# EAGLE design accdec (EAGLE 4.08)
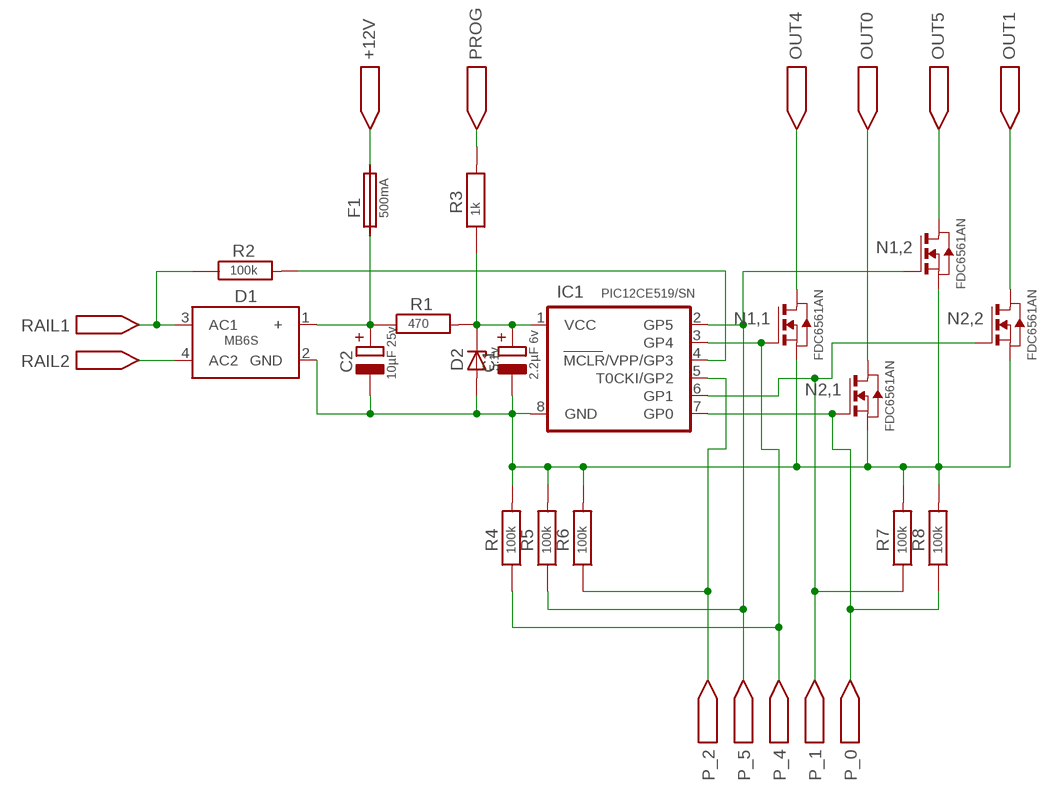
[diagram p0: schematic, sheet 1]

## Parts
+12V  PORT1*0.6  [CON_1*0.6]
C1  2.2µF 6v  ELKO_A  [CA]
C2  10µF 25v  ELKO_C  [CC]
D1  MB6S  [G1]
D2  5.1v  ZMM  [ZMM]
F1  500mA  FUSE  [1210]
IC1  PIC12CE519/SN  [SO8/SN]
N1  FDC6561AN  [SSOP6]
N2  FDC6561AN  [SSOP6]
OUT0  PORT1*0.6  [CON_1*0.6]
OUT1  PORT1*0.6  [CON_1*0.6]
OUT4  PORT1*0.6  [CON_1*0.6]
OUT5  PORT1*0.6  [CON_1*0.6]
P_0  PORT1*0.6  [CON_1*0.6]
P_1  PORT1*0.6  [CON_1*0.6]
P_2  PORT1*0.6  [CON_1*0.6]
P_4  PORT1*0.6  [CON_1*0.6]
P_5  PORT1*0.6  [CON_1*0.6]
PROG  PORT1*0.6  [CON_1*0.6]
R1  470  R-M1  [MICRO_MELF]
R2  100k  R-M1  [MICRO_MELF]
R3  1k  R-M1  [MICRO_MELF]
R4  100k  R-M1  [MICRO_MELF]
R5  100k  R-M1  [MICRO_MELF]
R6  100k  R-M1  [MICRO_MELF]
R7  100k  R-M1  [MICRO_MELF]
R8  100k  R-M1  [MICRO_MELF]
RAIL1  PORT1*0.6  [CON_1*0.6]
RAIL2  PORT1*0.6  [CON_1*0.6]

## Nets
+: C2.P$2(+) D1.1(+) F1.1 R1.P$1
DCCIN: IC1.4(MCLR/VPP/GP3) R2.P$2
F: +12V.P$1 F1.2
GND: C1.P$1(-) C2.P$1(-) D1.2(GND) D2.P$1(A) IC1.8(GND) N1.2(,2:S) N1.5(,1:S) N2.2(,2:S) N2.5(,1:S) R4.P$2 R5.P$2 R6.P$2 R7.P$2 R8.P$2
GP0: IC1.7(GP0) N2.1(,1:G) P_0.P$1 R8.P$1
GP1: IC1.6(GP1) N2.3(,2:G) P_1.P$1 R7.P$1
GP2: IC1.5(T0CKI/GP2) P_2.P$1 R6.P$1
GP4: IC1.3(GP4) N1.1(,1:G) P_4.P$1 R4.P$1
GP5: IC1.2(GP5) N1.3(,2:G) P_5.P$1 R5.P$1
OUT0: N2.6(,1:D) OUT0.P$1
OUT1: N2.4(,2:D) OUT1.P$1
OUT4: N1.6(,1:D) OUT4.P$1
OUT5: N1.4(,2:D) OUT5.P$1
PROG: PROG.P$1 R3.P$2
RAIL1: D1.3(AC1) R2.P$1 RAIL1.P$1
RAIL2: D1.4(AC2) RAIL2.P$1
VCC: C1.P$2(+) D2.P$2(K) IC1.1(VCC) R1.P$2 R3.P$1

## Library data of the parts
+12V OUT0 OUT1 OUT4 OUT5 P_0 P_1 P_2 P_4 P_5 PROG RAIL1 RAIL2 = NMRA-DCC_Decoder_Parts:PORT
C1 C2 = NMRA-DCC_Decoder_Parts:ELKO
D1 = NMRA-DCC_Decoder_Parts:MB6S: Rectifier s380 & mb6s
D2 = NMRA-DCC_Decoder_Parts:ZMM: DIODE
F1 = NMRA-DCC_Decoder_Parts:FUSE
IC1 = NMRA-DCC_Decoder_Parts:PIC12C*?: PIC12Cx5xx 8 bit Microchip Microcontroller with 2k byte PROM and 16 byte EEPROM
N1 N2 = NMRA-DCC_Decoder_Parts:FDC6561AN: FDC6561AN Dual N-Channel Logic Level PowerTrench MOSFET 2.5 A 30 V
R1-R8 = NMRA-DCC_Decoder_Parts:R-: Resistor

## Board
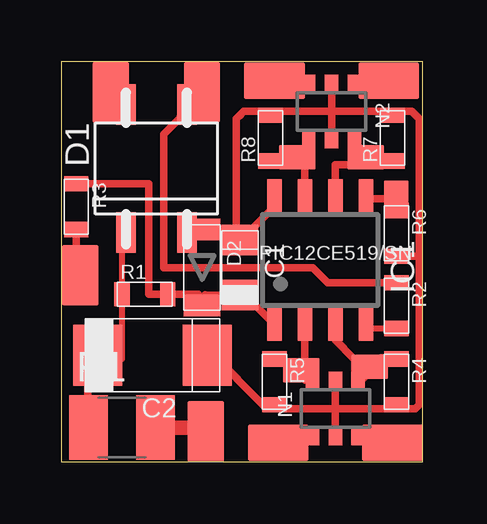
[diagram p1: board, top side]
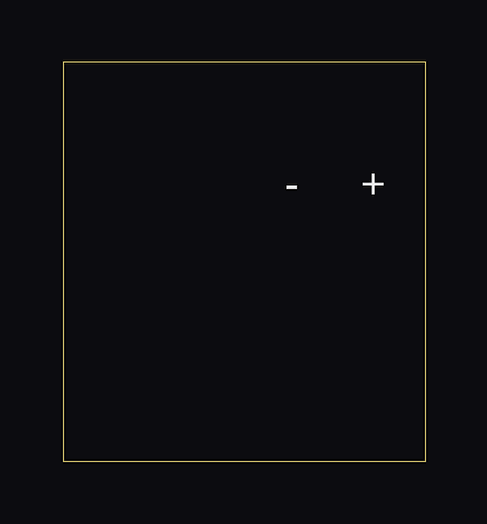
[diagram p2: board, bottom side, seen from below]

Size 15.07 x 16.66 mm. Coordinates in mm from the lower left corner, seen from the top.
Outline: 0,0 15.07,0 15.07,16.66 0,16.66 0,0
Copper layers used: Top

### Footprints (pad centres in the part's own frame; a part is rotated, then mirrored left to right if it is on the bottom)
CON_1*0.6 = smd 2.54 x 1.524: P$1 0,0
A_T = smd 1.27 x 1.524: P$1 -1.143,0; P$2 1.143,0
C_T = smd 2.032 x 2.54: P$1 -2.286,0; P$2 2.286,0
G1T = smd 1.676 x 0.813: 1 3.302,-1.27; 2 3.302,1.27; 3 -2.032,1.27; 4 -2.032,-1.27
Z_T = smd 0.889 x 1.524: P$1 -1.587,0; P$2 1.587,0
1210T = smd 1.6 x 2.7: 1 -1.4,0; 2 1.4,0
SO8/SN_T = smd 0.61 x 1.524: 1 -1.905,-2.6; 2 -0.635,-2.6; 3 0.635,-2.6; 4 1.905,-2.6; 5 1.905,2.6; 6 0.635,2.6; 7 -0.635,2.6; 8 -1.905,2.6
SSOP6T = smd 0.559 x 0.762: 1 -0.95,-1.15; 2 0,-1.15; 3 0.95,-1.15; 4 0.95,1.15; 5 0,1.15; 6 -0.95,1.15
CON_0.6*0.4 = smd 1.524 x 1.016: P$1 0,0
MICRO_MELF_T = smd 0.635 x 1.016: P$1 -0.953,0; P$2 0.953,0
MICRO_MELF = smd 0.635 x 1.016: P$1 -0.953,0; P$2 0.953,0

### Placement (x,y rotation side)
+12V  6.03,1.27 270 top
C1  2.2µF 6v  [A_T]  7.46,8.09 270 top
C2  10µF 25v  [C_T]  3.8,4.44 180 top
D1  MB6S  [G1T]  3.96,12.85 270 top
D2  5.1v  [Z_T]  5.87,8.09 270 top
F1  500mA  [1210T]  2.53,1.42 0 top
IC1  PIC12CE519/SN  [SO8/SN_T]  10.79,8.41 0 top
N1  FDC6561AN  [SSOP6T]  11.42,2.22 180 top
N2  FDC6561AN  [SSOP6T]  11.27,14.6 0 top
OUT0  8.88,15.87 0 top
OUT1  13.65,15.87 0 top
OUT4  13.81,0.79 0 top
OUT5  9.04,0.79 0 top
P_0  [CON_0.6*0.4]  9.84,12.7 0 top
P_1  [CON_0.6*0.4]  12.69,12.7 0 top
P_2  [CON_0.6*0.4]  13.96,10.95 90 top
P_4  [CON_0.6*0.4]  12.85,3.96 0 top
P_5  [CON_0.6*0.4]  9.99,3.81 0 top
PROG  0.79,7.77 270 top
R1  470  [MICRO_MELF_T]  3.49,6.98 0 top
R2  100k  [MICRO_MELF_T]  13.96,6.5 270 top
R3  1k  [MICRO_MELF_T]  0.63,10.63 270 top
R4  13.96,3.33 270 top
R5  8.88,3.33 270 top
R6  13.96,9.52 270 top
R7  13.81,13.49 90 top
R8  8.73,13.49 90 top
RAIL1  5.87,15.39 90 top
RAIL2  2.06,15.39 90 top

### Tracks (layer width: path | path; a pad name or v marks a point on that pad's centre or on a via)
+
  Top 0.254: 1.9,4.28 2.53,4.28 R1.P$1 2.53,9.68
  Top 0.305: 1.1,1.74 1.1,4.28 1.9,4.28 | C2.P$2 1.74,4.6 1.9,4.44 | D1.1 2.66,9.55 2.53,9.68
  Top 0.406: 1.9,4.28 1.9,4.44 | F1.1 1.1,1.74
DCCIN
  Top 0.254: IC1.4 12.69,5.55 R2.P$2
F
  Top 0.305: 6.03,1.42 +12V.P$1
  Top 0.61: F1.2 6.03,1.42
GND
  Top 0.254: D1.2 7.3,9.55 C1.P$1 | D2.P$1 7.49,9.39
  Top 0.305: 7.49,9.39 C1.P$1 | 6.18,4.6 8.41,2.38 R5.P$2 9.2,2.38 9.36,2.22 11.42,2.22 | 11.42,2.22 N1.5 | 11.42,2.22 N1.2 | R4.P$2 13.96,2.22 11.42,2.22 | C2.P$1 6.18,4.6 | 6.18,4.6 8.57,2.22 14.76,2.22 14.92,2.38 14.92,8.57 | 8.72,14.6 7.61,14.6 | 7.61,14.6 7.45,14.44 | 7.45,14.44 | 7.3,14.28 7.45,14.44 | 7.3,9.68 D2.P$1 | 7.3,9.84 7.3,9.68 | 7.3,9.68 7.3,9.52 | 14.12,14.6 13.8,14.6 | 11.26,14.6 8.72,14.6 | 11.26,14.6 11.26,13.49 | 13.8,14.6 R7.P$2 13.96,14.44 14.12,14.6 | 13.8,14.6 11.26,14.6 | 11.26,13.49 N2.2 | 11.26,13.49 N2.5 | 7.3,14.28 7.3,9.84 | 7.61,14.6 7.3,14.28 | 8.72,14.6 R8.P$2 | 8.72,14.6 7.61,14.6 | 14.12,14.6 14.6,14.6 14.92,14.28 14.92,8.57 | R6.P$2 | 14.92,8.57 R6.P$2 | C1.P$1 7.45,9.2 | C1.P$1 | 7.3,9.84 7.45,9.52 C1.P$1 | IC1.8 8.88,10.63 7.93,9.68 7.3,9.68 7.3,9.84
GP0
  Top 0.254: 10.31,13.49 N2.1 10.15,13.13 | 9.99,12.69 P_0.P$1 | 9.99,12.69 10.31,13.49 | 10.31,13.49 | 9.99,12.69 | 9.99,12.69 | 10.15,13.13 9.99,12.69 | 10.15,12.54 10.15,13.13
  Top 0.305: IC1.7 10.15,12.54 R8.P$1
GP1
  Top 0.127: 12.22,13.49 N2.3
  Top 0.254: 12.22,12.38 12.22,12.85 N2.3 | 11.42,11.11 11.42,12.38 | 12.22,13.49 P_1.P$1
  Top 0.305: 11.42,12.38 12.22,12.38 | R7.P$1 12.22,12.54 12.06,12.38 11.42,12.38 | IC1.6 11.42,11.11 11.42,12.38
GP2
  Top 0.254: IC1.5 12.75,10.95 13.8,10.95 P_2.P$1
  Top 0.305: R6.P$1 13.96,10.79 13.8,10.95 12.69,10.95 IC1.5
GP4
  Top 0.254: N1.1 12.22,3.65 12.22,4.28 | 11.42,5.07 IC1.3 | 12.38,3.49 P_4.P$1
  Top 0.305: 12.22,4.28 11.42,5.07 | 12.38,3.49 | N1.1 12.37,3.48 12.38,3.49
  Top 0.406: N1.1 12.41,3.37 13.33,4.28 R4.P$1
GP5
  Top 0.254: P_5.P$1 10.15,3.49 | 10.15,3.49 10.47,3.49 10.47,3.21 N1.3 10.15,3.37 10.15,3.49
  Top 0.305: 10.15,3.49 IC1.2
  Top 0.406: P_5.P$1 9.84,3.65 9.2,4.28 R5.P$1 | P_5.P$1
OUT0
  Top 0.406: OUT0.P$1 8.88,15.71 10.31,15.71 N2.6
OUT1
  Top 0.406: OUT1.P$1 13.65,15.71 12.22,15.71 N2.4
OUT4
  Top 0.406: OUT4.P$1 | OUT4.P$1 13.8,1.11 12.53,1.11 12.53,1.07 N1.6
OUT5
  Top 0.406: OUT5.P$1 9.04,1.11 10.47,1.11 N1.4
PROG
  Top 0.254: PROG.P$1 0.63,7.77
  Top 0.305: 0.63,7.77 R3.P$2
RAIL1
  Top 0.254: 5.07,14.76 4.91,14.28 RAIL1.P$1
  Top 0.305: R2.P$1 11.11,7.46 10.47,8.09 4.28,8.09 4.28,13.65 4.91,14.28 | 5.07,14.76 5.23,14.76 D1.3
RAIL2
  Top 0.406: RAIL2.P$1 | D1.4 2.57,14.89 RAIL2.P$1
VCC
  Top 0.305: R3.P$1 3.64,11.58 3.64,6.98 R1.P$2 5.71,6.98 D2.P$2 6.03,6.66 5.99,6.95 C1.P$2 7.8,6.79 8.78,5.81 IC1.1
